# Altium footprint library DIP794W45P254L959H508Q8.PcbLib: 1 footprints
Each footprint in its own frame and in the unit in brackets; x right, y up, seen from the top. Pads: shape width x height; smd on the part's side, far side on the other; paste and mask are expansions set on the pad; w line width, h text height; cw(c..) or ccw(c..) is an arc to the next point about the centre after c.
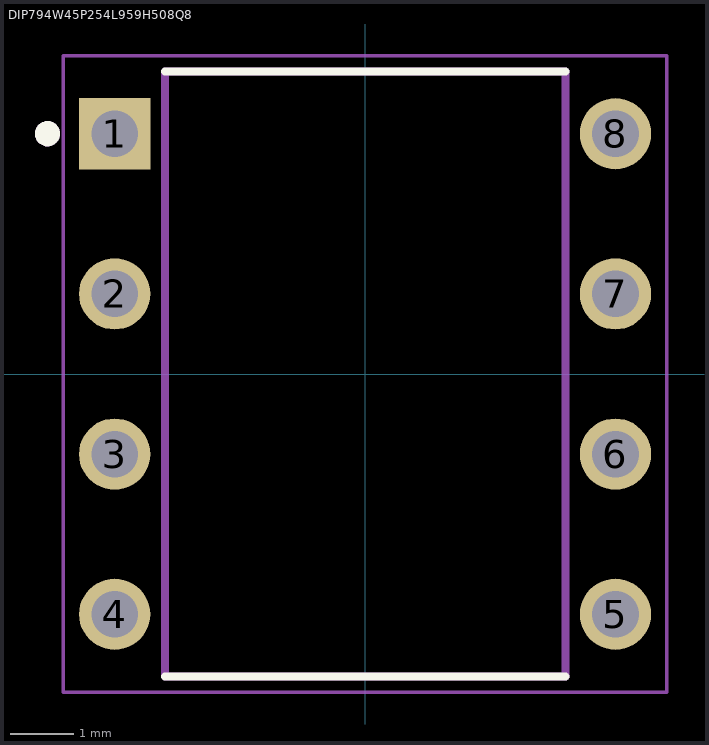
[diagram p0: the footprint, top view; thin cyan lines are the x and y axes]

## DIP794W45P254L959H508Q8 [mm]
height 5.08
pads (8):
  rect 1.13x1.13 / inner round 1.13 / far side rect 1.13x1.13 hole 0.74 mask+0.102: 1(-3.97,3.81)
  round 1.13 hole 0.74 mask+0.102: 2(-3.97,1.27) 3(-3.97,-1.27) 4(-3.97,-3.81) 5(3.97,-3.81) 6(3.97,-1.27) 7(3.97,1.27) 8(3.97,3.81)
Top Overlay:
  circle w0.2: c-5.035,3.81 r0.1
  lines w0.127: -3.175,-4.795 3.175,-4.795 ; -3.175,4.795 3.175,4.795
Assembly Top:
  circle w0.2: c-5.035,3.81 r0.1
  lines w0.127: -3.175,-4.795 -3.175,4.795 3.175,4.795 3.175,-4.795 -3.175,-4.795
Courtyard Top:
  lines w0.05: -4.785,-5.045 -4.785,5.045 4.785,5.045 4.785,-5.045 -4.785,-5.045
3D body "step_temp.STEP": height 5.08, standoff -3.18, extent -4.095,-4.795 4.095,4.795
